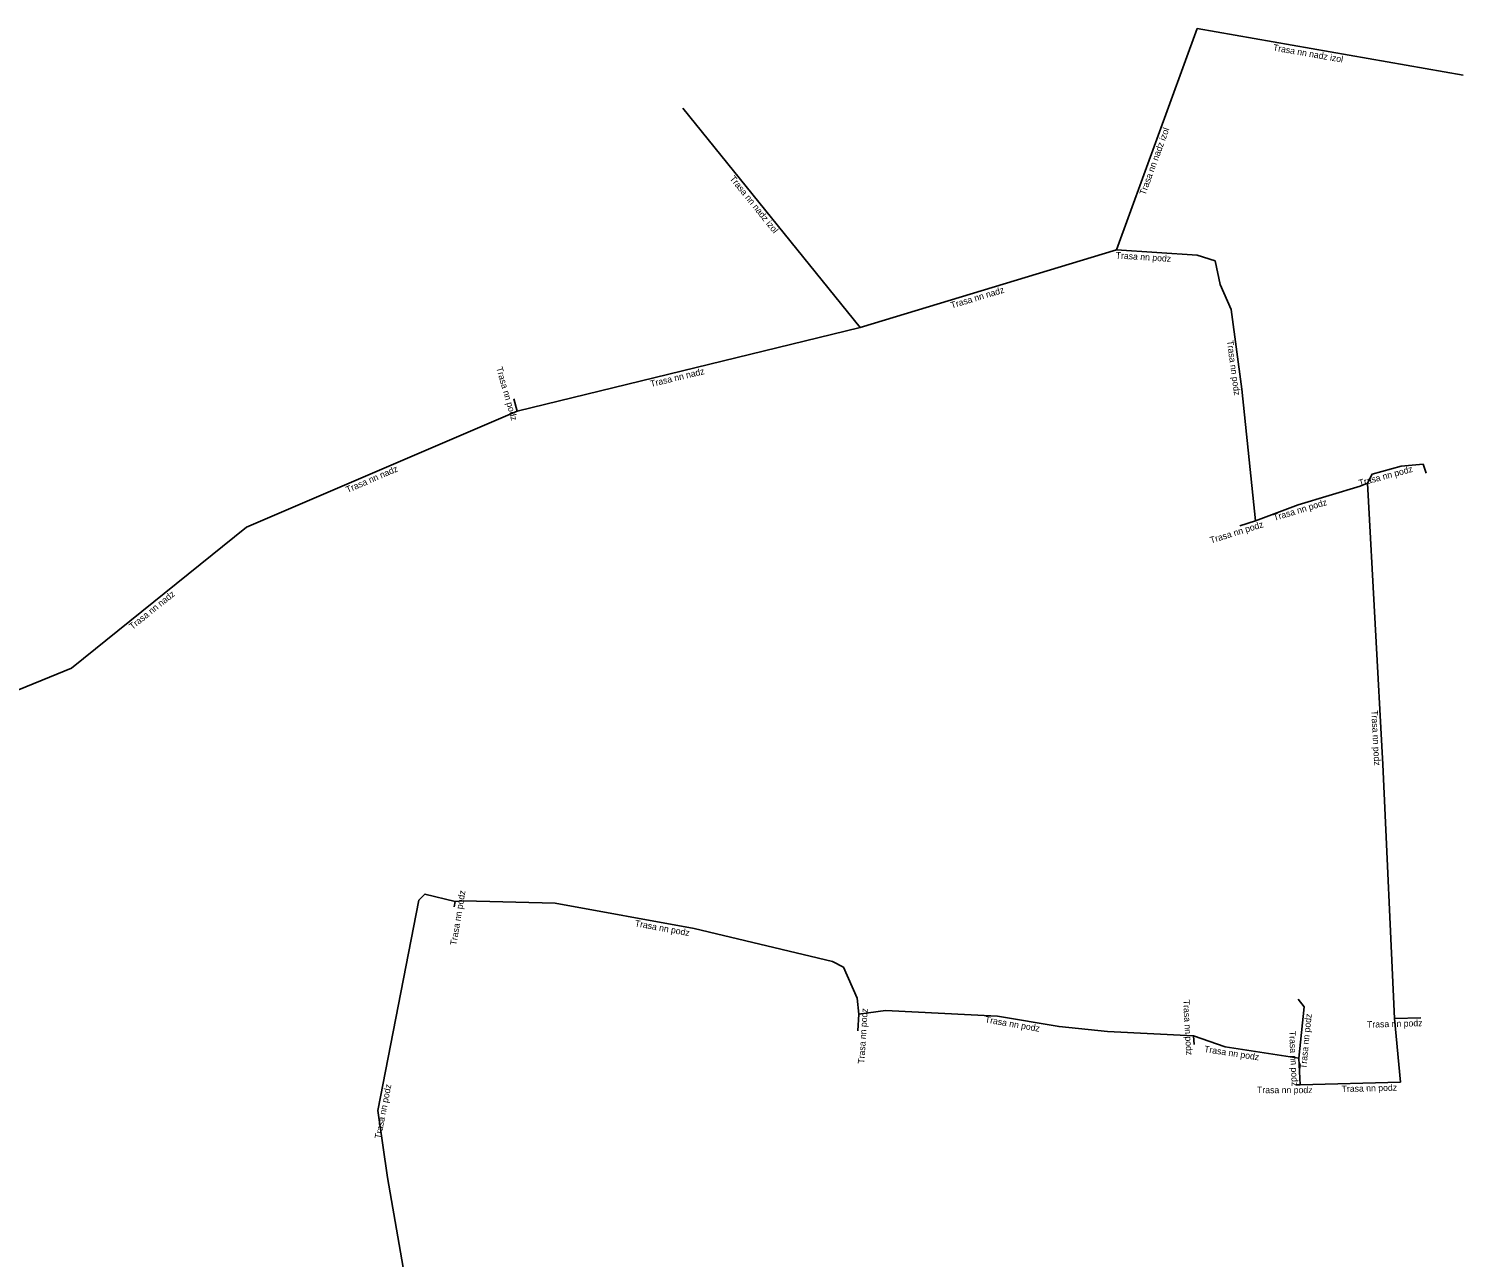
# Model space of a CAD drawing. Extents: x -682739 to -681564, y -1060091 to -1059590.
# Drawn here: x -682002.1 to -681891.6, y -1059744.3 to -1059649.6 of the extents above; entities that cross this region are included whole.
import ezdxf

# ---------------------------------------------------------------- set-up
doc = ezdxf.new("R2010")
doc.units = 0
doc.layers.add('Popiskový text - Ostatní atributy Trasy', color=7, linetype='Continuous')
doc.layers.add('Spojnice NN', color=7, linetype='Continuous')

msp = doc.modelspace()

# ---------------------------------------------------------------- linework, layer by layer
at = {"layer": 'Spojnice NN'}
for points in [[(-681912.13, -1059649.6), (-681918.33, -1059666.65)], [(-681891.62, -1059653.19), (-681912.13, -1059649.6)], [(-681951.74, -1059655.73), (-681938.08, -1059672.62)], [(-681918.33, -1059666.65), (-681938.08, -1059672.62)], [(-681912.12, -1059667.05), (-681918.33, -1059666.65)], [(-681907.64, -1059687.53), (-681908.68, -1059677.38), (-681909.51, -1059671.23), (-681910.35, -1059669.31), (-681910.74, -1059667.49), (-681912.12, -1059667.05)], [(-681938.08, -1059672.62), (-681964.5, -1059679.06)], [(-681964.5, -1059679.06), (-681964.77, -1059678.12)], [(-681964.5, -1059679.06), (-681985.37, -1059688.02)], [(-681899, -1059684.62), (-681898.63, -1059683.92), (-681896.42, -1059683.32), (-681894.72, -1059683.16), (-681894.48, -1059683.84)], [(-681899, -1059684.62), (-681899.57, -1059684.86), (-681904.35, -1059686.3), (-681907.64, -1059687.53)], [(-681896.93, -1059725.87), (-681897.83, -1059706.3), (-681899, -1059684.62)], [(-681907.64, -1059687.53), (-681908.83, -1059687.9)], [(-681985.37, -1059688.02), (-681998.83, -1059698.88)], [(-681998.83, -1059698.88), (-682013.37, -1059704.8)], [(-681973.04, -1059750.26), (-681972.7, -1059748.45), (-681974.51, -1059738.12), (-681975.24, -1059732.95), (-681972.09, -1059716.76), (-681971.62, -1059716.28), (-681969.28, -1059716.84)], [(-681969.28, -1059716.84), (-681969.35, -1059717.26)], [(-681969.28, -1059716.84), (-681968.64, -1059716.81), (-681961.57, -1059716.99), (-681950.88, -1059718.94), (-681940.22, -1059721.48), (-681939.36, -1059721.92), (-681938.31, -1059724.29), (-681938.18, -1059725.54)], [(-681938.18, -1059725.54), (-681936.14, -1059725.26), (-681927.51, -1059725.68), (-681922.76, -1059726.49), (-681919.03, -1059726.86), (-681912.4, -1059727.21)], [(-681904.34, -1059724.38), (-681903.89, -1059724.96), (-681904.29, -1059728.92)], [(-681938.18, -1059725.54), (-681938.26, -1059726.82)], [(-681904.19, -1059730.97), (-681896.46, -1059730.77), (-681896.93, -1059725.87)], [(-681896.93, -1059725.87), (-681894.88, -1059725.81)], [(-681912.4, -1059727.21), (-681909.96, -1059728.05), (-681904.29, -1059728.92)], [(-681912.4, -1059727.21), (-681912.36, -1059727.87)], [(-681904.29, -1059728.92), (-681904.19, -1059730.97)], [(-681904.19, -1059730.97), (-681904.53, -1059730.97)]]:
    msp.add_lwpolyline(points, dxfattribs=at)

# ---------------------------------------------------------------- texts
at = {"layer": 'Popiskový text - Ostatní atributy Trasy'}
for s, rotation, p in [('Trasa nn nadz izol', 350.0786, (-681906.31, -1059651.28)), ('Trasa nn nadz izol', 70.0226, (-681916.12, -1059662.47)), ('Trasa nn nadz izol', 308.9683, (-681948.17, -1059661.17)), ('Trasa nn podz', 356.3145, (-681918.41, -1059667.3)), ('Trasa nn nadz', 16.8267, (-681931.03, -1059671.17)), ('Trasa nn podz', 277.6862, (-681909.84, -1059673.65)), ('Trasa nn podz', 286.0343, (-681966.13, -1059675.74)), ('Trasa nn nadz', 13.6857, (-681954.19, -1059677.22)), ('Trasa nn nadz', 23.241, (-681977.57, -1059685.38)), ('Trasa nn podz', 15.1893, (-681899.6, -1059684.86)), ('Trasa nn podz', 16.7652, (-681906.17, -1059687.53)), ('Trasa nn podz', 17.2717, (-681911.05, -1059689.27)), ('Trasa nn nadz', 38.8931, (-681994.15, -1059695.93)), ('Trasa nn podz', 273.0891, (-681898.71, -1059702.13)), ('Trasa nn podz', 80.5377, (-681969.19, -1059720.26)), ('Trasa nn podz', 349.6621, (-681955.47, -1059718.76)), ('Trasa nn podz', 86.2812, (-681937.77, -1059729.36)), ('Trasa nn podz', 273.3614, (-681913.21, -1059724.44)), ('Trasa nn podz', 350.2677, (-681928.5, -1059726.17)), ('Trasa nn podz', 84.2321, (-681903.72, -1059729.77)), ('Trasa nn podz', 1.6765, (-681899.03, -1059726.58)), ('Trasa nn podz', 272.7927, (-681905.04, -1059726.83)), ('Trasa nn podz', 351.2766, (-681911.61, -1059728.45)), ('Trasa nn podz', 78.9898, (-681975.01, -1059735.17)), ('Trasa nn podz', 1.4821, (-681900.99, -1059731.54))]:
    msp.add_text(s, height=0.5, rotation=rotation, dxfattribs=at).set_placement(p)
msp.add_text('Trasa nn podz', height=0.5, dxfattribs=at).set_placement((-681907.51, -1059731.62))

doc.saveas('drawing.dxf')
